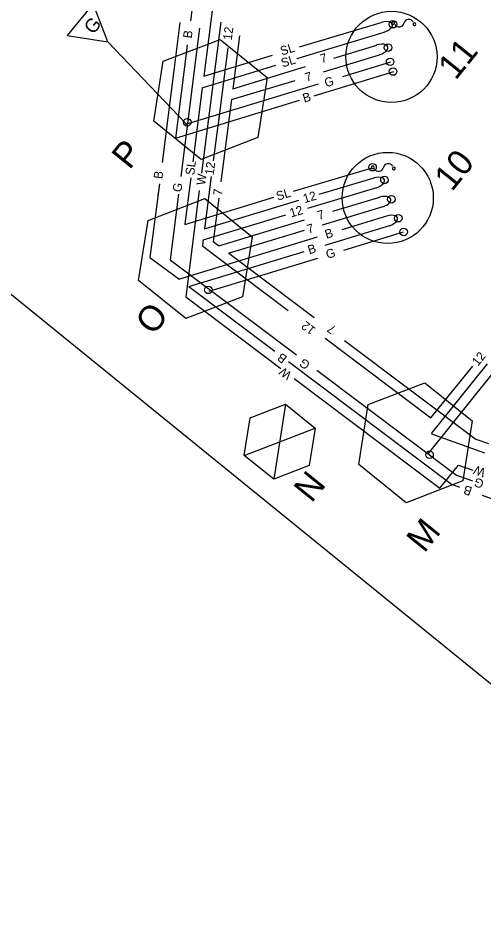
# Model space of a CAD drawing. Extents: x 592613 to 600223, y 4837996 to 4840103.
# Drawn here: x 592734.31 to 592751.79, y 4838886.03 to 4838919.81 of the extents above; entities that cross this region are included whole.
import ezdxf

# ---------------------------------------------------------------- set-up
doc = ezdxf.new("R2010")
doc.units = 0
for name, color, linetype in [('ENG_BORDER', 7, 'Continuous'), ('TCS_ELEC-CHAMBER-NEW', 7, 'Continuous'), ('TCS_FUSE', 7, 'Continuous'), ('TCS_PLATE', 7, 'Continuous'), ('TCS_POLE-NEW', 7, 'Continuous'), ('TCS_WR_12', 7, 'Continuous'), ('TCS_WR_7', 7, 'Continuous'), ('TCS_WR_B', 7, 'Continuous'), ('TCS_WR_G', 7, 'Continuous'), ('TCS_WR_SL', 7, 'Continuous'), ('TCS_WR_W', 7, 'Continuous')]:
    doc.layers.add(name, color=color, linetype=linetype)

msp = doc.modelspace()

# ---------------------------------------------------------------- linework, layer by layer
at = {"layer": 'ENG_BORDER'}
msp.add_lwpolyline([(592658.479, 4838970.843), (592762.862, 4838886.033)], dxfattribs=at)
at = {"layer": 'TCS_ELEC-CHAMBER-NEW'}
for p, q in [((592739.757, 4838918.185), (592741.885, 4838919.005)), ((592741.885, 4838919.005), (592743.659, 4838917.572)), ((592739.404, 4838915.933), (592739.757, 4838918.185)), ((592743.659, 4838917.572), (592743.305, 4838915.32)), ((592741.178, 4838914.5), (592739.404, 4838915.933)), ((592743.305, 4838915.32), (592741.178, 4838914.5)), ((592739.185, 4838912.211), (592741.313, 4838913.031)), ((592741.313, 4838913.031), (592743.087, 4838911.598)), ((592738.832, 4838909.958), (592739.185, 4838912.211)), ((592743.087, 4838911.598), (592742.733, 4838909.346)), ((592740.605, 4838908.526), (592738.832, 4838909.958)), ((592742.733, 4838909.346), (592740.605, 4838908.526)), ((592747.444, 4838905.298), (592749.572, 4838906.118)), ((592749.572, 4838906.118), (592751.345, 4838904.686)), ((592743.01, 4838904.803), (592744.34, 4838905.316)), ((592744.34, 4838905.316), (592743.898, 4838902.5)), ((592744.34, 4838905.316), (592745.449, 4838904.42)), ((592747.09, 4838903.046), (592747.444, 4838905.298)), ((592742.789, 4838903.395), (592743.01, 4838904.803)), ((592742.789, 4838903.395), (592745.449, 4838904.42)), ((592745.449, 4838904.42), (592745.228, 4838903.012)), ((592751.345, 4838904.686), (592750.992, 4838902.433)), ((592743.898, 4838902.5), (592742.789, 4838903.395)), ((592748.864, 4838901.613), (592747.09, 4838903.046)), ((592745.228, 4838903.012), (592743.898, 4838902.5)), ((592750.992, 4838902.433), (592748.864, 4838901.613))]:
    msp.add_line(p, q, dxfattribs=at)
at = {"layer": 'TCS_FUSE'}
for centre, radius, start, end in [((592748.384, 4838919.622), 0.0513, 168.9594, 348.9594), ((592748.384, 4838919.622), 0.0513, 348.9594, 168.9594), ((592748.601, 4838919.66), 0.189, 209.5934, 346.2421), ((592748.968, 4838919.57), 0.189, 29.5934, 166.2421), ((592749.177, 4838919.574), 0.0513, 348.9594, 168.9594), ((592749.177, 4838919.574), 0.0513, 168.9594, 348.9594), ((592747.614, 4838914.205), 0.0513, 168.9594, 348.9594), ((592747.614, 4838914.205), 0.0513, 348.9594, 168.9594), ((592747.831, 4838914.243), 0.189, 209.5934, 346.2421), ((592748.197, 4838914.154), 0.189, 29.5934, 166.2421), ((592748.406, 4838914.158), 0.0513, 348.9594, 168.9594), ((592748.406, 4838914.158), 0.0513, 168.9594, 348.9594)]:
    msp.add_arc(centre, radius, start, end, dxfattribs=at)
at = {"layer": 'TCS_PLATE'}
for p, q in [((592737.122, 4838920.344), (592736.155, 4838919.147)), ((592737.675, 4838918.908), (592737.122, 4838920.344)), ((592736.155, 4838919.147), (592737.675, 4838918.908))]:
    msp.add_line(p, q, dxfattribs=at)
at = {"layer": 'TCS_POLE-NEW'}
for centre in [(592748.317, 4838918.349), (592748.175, 4838913.057)]:
    msp.add_circle(centre, 1.71, dxfattribs=at)
at = {"layer": 'TCS_WR_12'}
for p, q in [((592742.176, 4838918.692), (592741.964, 4838917.025)), ((592741.964, 4838917.025), (592741.813, 4838915.836)), ((592741.9, 4838916.526), (592741.633, 4838914.444)), ((592741.559, 4838913.866), (592741.306, 4838911.892)), ((592745.607, 4838913.203), (592747.663, 4838913.813)), ((592745.173, 4838912.678), (592747.771, 4838913.449)), ((592741.306, 4838911.892), (592744.837, 4838912.967)), ((592741.253, 4838911.478), (592744.358, 4838912.423)), ((592741.253, 4838911.478), (592741.225, 4838911.254)), ((592741.225, 4838911.254), (592741.65, 4838910.934)), ((592741.65, 4838910.934), (592744.442, 4838908.833)), ((592745.831, 4838907.789), (592749.797, 4838904.805)), ((592749.797, 4838904.805), (592751.37, 4838906.748)), ((592749.819, 4838904.21), (592751.916, 4838906.824)), ((592749.818, 4838904.209), (592751.806, 4838903.484))]:
    msp.add_line(p, q, dxfattribs=at)
msp.add_ellipse((592747.691, 4838913.619), major_axis=(-0.364, -0.111), ratio=0.5, start_param=1.570796, end_param=4.712389, dxfattribs=at)
at = {"layer": 'TCS_WR_7'}
for p, q in [((592742.616, 4838919.139), (592742.362, 4838917.147)), ((592746.154, 4838918.306), (592747.761, 4838918.795)), ((592745.763, 4838917.79), (592747.872, 4838918.431)), ((592742.362, 4838917.147), (592745.093, 4838917.983)), ((592742.312, 4838916.747), (592744.702, 4838917.467)), ((592742.311, 4838916.747), (592741.919, 4838913.663)), ((592741.84, 4838913.043), (592741.709, 4838912.015)), ((592746.12, 4838912.563), (592747.879, 4838913.085)), ((592745.729, 4838912.046), (592748.002, 4838912.731)), ((592741.842, 4838911.26), (592745.058, 4838912.24)), ((592741.707, 4838912.015), (592741.633, 4838911.413)), ((592742.208, 4838910.983), (592745.057, 4838911.841)), ((592741.633, 4838911.416), (592741.832, 4838911.266)), ((592742.213, 4838910.979), (592745.415, 4838908.571)), ((592746.559, 4838907.711), (592751.485, 4838904.005)), ((592751.485, 4838904.005), (592751.955, 4838903.834))]:
    msp.add_line(p, q, dxfattribs=at)
for centre in [(592747.816, 4838918.615), (592747.923, 4838912.901)]:
    msp.add_ellipse(centre, major_axis=(-0.364, -0.111), ratio=0.5, start_param=1.570796, end_param=4.712389, dxfattribs=at)
at = {"layer": 'TCS_WR_B'}
for p, q in [((592741.402, 4838924.645), (592740.773, 4838919.704)), ((592740.381, 4838919.636), (592740.153, 4838917.844)), ((592740.629, 4838918.575), (592740.211, 4838915.305)), ((592740.658, 4838918.803), (592740.629, 4838918.575)), ((592740.153, 4838917.844), (592739.712, 4838914.386)), ((592745.421, 4838916.891), (592748.403, 4838917.799)), ((592740.211, 4838915.305), (592744.865, 4838916.722)), ((592739.61, 4838913.583), (592739.259, 4838910.824)), ((592739.568, 4838913.255), (592739.553, 4838913.134)), ((592746.461, 4838911.872), (592748.148, 4838912.384)), ((592745.835, 4838911.286), (592748.292, 4838912.031)), ((592740.342, 4838910.01), (592745.54, 4838911.592)), ((592739.259, 4838910.824), (592740.335, 4838910.014)), ((592740.718, 4838909.727), (592745.046, 4838911.044)), ((592740.718, 4838909.727), (592743.941, 4838907.302)), ((592744.457, 4838906.914), (592750.567, 4838902.318)), ((592750.567, 4838902.318), (592750.871, 4838902.207)), ((592751.712, 4838901.901), (592752.467, 4838901.626))]:
    msp.add_line(p, q, dxfattribs=at)
msp.add_ellipse((592748.179, 4838912.195), major_axis=(-0.364, -0.111), ratio=0.5, start_param=1.570796, end_param=4.712389, dxfattribs=at)
at = {"layer": 'TCS_WR_G'}
for p, q in [((592741.12, 4838919.421), (592740.994, 4838918.433)), ((592740.599, 4838915.846), (592737.675, 4838918.908)), ((592740.994, 4838918.433), (592740.411, 4838913.855)), ((592746.495, 4838917.615), (592748.293, 4838918.162)), ((592740.601, 4838915.821), (592745.575, 4838917.335)), ((592740.328, 4838913.199), (592740.013, 4838910.732)), ((592746.524, 4838911.097), (592748.769, 4838911.78)), ((592741.483, 4838909.562), (592745.551, 4838910.801)), ((592740.013, 4838910.732), (592744.752, 4838907.167)), ((592745.521, 4838906.589), (592750.75, 4838902.656)), ((592749.701, 4838903.459), (592752.14, 4838906.5)), ((592750.75, 4838902.656), (592751.361, 4838902.433))]:
    msp.add_line(p, q, dxfattribs=at)
at = {"layer": 'TCS_WR_SL'}
for p, q in [((592741.655, 4838920.617), (592741.275, 4838917.629)), ((592744.865, 4838918.729), (592747.932, 4838919.643)), ((592744.982, 4838918.346), (592748.037, 4838919.276)), ((592741.275, 4838917.629), (592743.856, 4838918.42)), ((592744.78, 4838918.284), (592744.982, 4838918.346)), ((592741.219, 4838917.194), (592743.973, 4838918.037)), ((592741.219, 4838917.194), (592740.865, 4838914.411)), ((592744.643, 4838913.313), (592747.554, 4838914.178)), ((592740.789, 4838913.812), (592740.568, 4838912.08)), ((592740.566, 4838912.063), (592743.907, 4838913.08))]:
    msp.add_line(p, q, dxfattribs=at)
msp.add_ellipse((592747.983, 4838919.46), major_axis=(-0.364, -0.111), ratio=0.5, start_param=1.570796, end_param=4.712389, dxfattribs=at)
at = {"layer": 'TCS_WR_W'}
for p, q in [((592741.915, 4838919.652), (592741.193, 4838913.989)), ((592741.109, 4838913.338), (592740.6, 4838909.34)), ((592740.6, 4838909.34), (592744.168, 4838906.656)), ((592744.665, 4838906.282), (592750.132, 4838902.17)), ((592750.132, 4838902.17), (592750.824, 4838903.033)), ((592750.824, 4838903.033), (592751.364, 4838902.837))]:
    msp.add_line(p, q, dxfattribs=at)
for centre in [(592748.372, 4838919.576), (592748.188, 4838918.699), (592748.266, 4838918.164), (592748.377, 4838917.8), (592740.659, 4838915.895), (592747.605, 4838914.209), (592748.054, 4838913.73), (592748.314, 4838913.004), (592748.573, 4838912.295), (592748.769, 4838911.78), (592741.446, 4838909.606), (592749.744, 4838903.419)]:
    msp.add_circle(centre, 0.142, dxfattribs=at)

# ---------------------------------------------------------------- texts
at = {"layer": 'TCS_ELEC-CHAMBER-NEW'}
for s, p in [('P', (592738.491, 4838914.083)), ('O', (592739.38, 4838907.865)), ('N', (592745.32, 4838901.579)), ('M', (592749.543, 4838899.701))]:
    msp.add_text(s, height=0.95, rotation=51.0744, dxfattribs=at).set_placement(p)
at = {"layer": 'TCS_PLATE'}
msp.add_text('G', height=0.513, rotation=51.0744, dxfattribs=at).set_placement((592737.134, 4838919.165))
at = {"layer": 'TCS_POLE-NEW'}
for s, p in [('11', (592750.722, 4838917.447)), ('10', (592750.584, 4838913.268))]:
    msp.add_text(s, height=0.95, rotation=51.0744, dxfattribs=at).set_placement(p)
at = {"layer": 'TCS_WR_12'}
for rotation, p in [(82.7426, (592742.326, 4838918.963)), (82.7426, (592741.645, 4838913.899)), (16.9279, (592745.057, 4838912.858)), (16.9279, (592744.554, 4838912.32)), (143.0494, (592745.498, 4838908.157)), (51.273, (592751.561, 4838906.724))]:
    msp.add_text('12', height=0.3325, rotation=rotation, dxfattribs=at).set_placement(p)
at = {"layer": 'TCS_WR_7'}
for height, rotation, p in [(0.332, 16.9279, (592745.699, 4838918.107)), (0.332, 16.9279, (592745.131, 4838917.409)), (0.332, 82.7426, (592741.955, 4838913.133)), (0.332, 16.9279, (592745.595, 4838912.229)), (0.332, 16.9279, (592745.204, 4838911.713)), (0.333, 143.0494, (592746.263, 4838908.185))]:
    msp.add_text('7', height=height, rotation=rotation, dxfattribs=at).set_placement(p)
at = {"layer": 'TCS_WR_B'}
for height, rotation, p in [(0.332, 82.7426, (592740.823, 4838919.032)), (0.332, 16.9279, (592745.043, 4838916.631)), (0.332, 82.7426, (592739.721, 4838913.754)), (0.333, 16.9279, (592745.875, 4838911.52)), (0.333, 16.9279, (592745.234, 4838910.937)), (0.333, 143.0494, (592744.429, 4838907.085)), (0.333, 159.9803, (592751.371, 4838902.181))]:
    msp.add_text('B', height=height, rotation=rotation, dxfattribs=at).set_placement(p)
at = {"layer": 'TCS_WR_G'}
for height, rotation, p in [(0.333, 16.9279, (592745.857, 4838917.207)), (0.332, 82.7426, (592740.433, 4838913.261)), (0.332, 16.9279, (592745.915, 4838910.766)), (0.333, 143.0494, (592745.295, 4838906.851)), (0.333, 159.9803, (592751.813, 4838902.45))]:
    msp.add_text('G', height=height, rotation=rotation, dxfattribs=at).set_placement(p)
at = {"layer": 'TCS_WR_SL'}
for rotation, p in [(16.9279, (592744.202, 4838918.399)), (16.9279, (592744.232, 4838917.951)), (82.7426, (592740.914, 4838913.895)), (16.9279, (592744.049, 4838912.953))]:
    msp.add_text('SL', height=0.3325, rotation=rotation, dxfattribs=at).set_placement(p)
at = {"layer": 'TCS_WR_W'}
for height, rotation, p in [(0.332, 82.7426, (592741.327, 4838913.52)), (0.333, 143.0494, (592744.603, 4838906.47)), (0.333, 159.9803, (592751.871, 4838902.879))]:
    msp.add_text('W', height=height, rotation=rotation, dxfattribs=at).set_placement(p)

doc.saveas('drawing.dxf')
